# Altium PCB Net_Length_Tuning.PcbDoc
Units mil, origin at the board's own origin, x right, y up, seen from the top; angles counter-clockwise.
Board outline 6000 x 4000 mil, 4 copper layers (Component Side, Ground Plane, Power Plane, Solder Side); 10 components, 17 nets, 432 pads, 0 vias.
Unrouted connection lines stored in the file: 101.
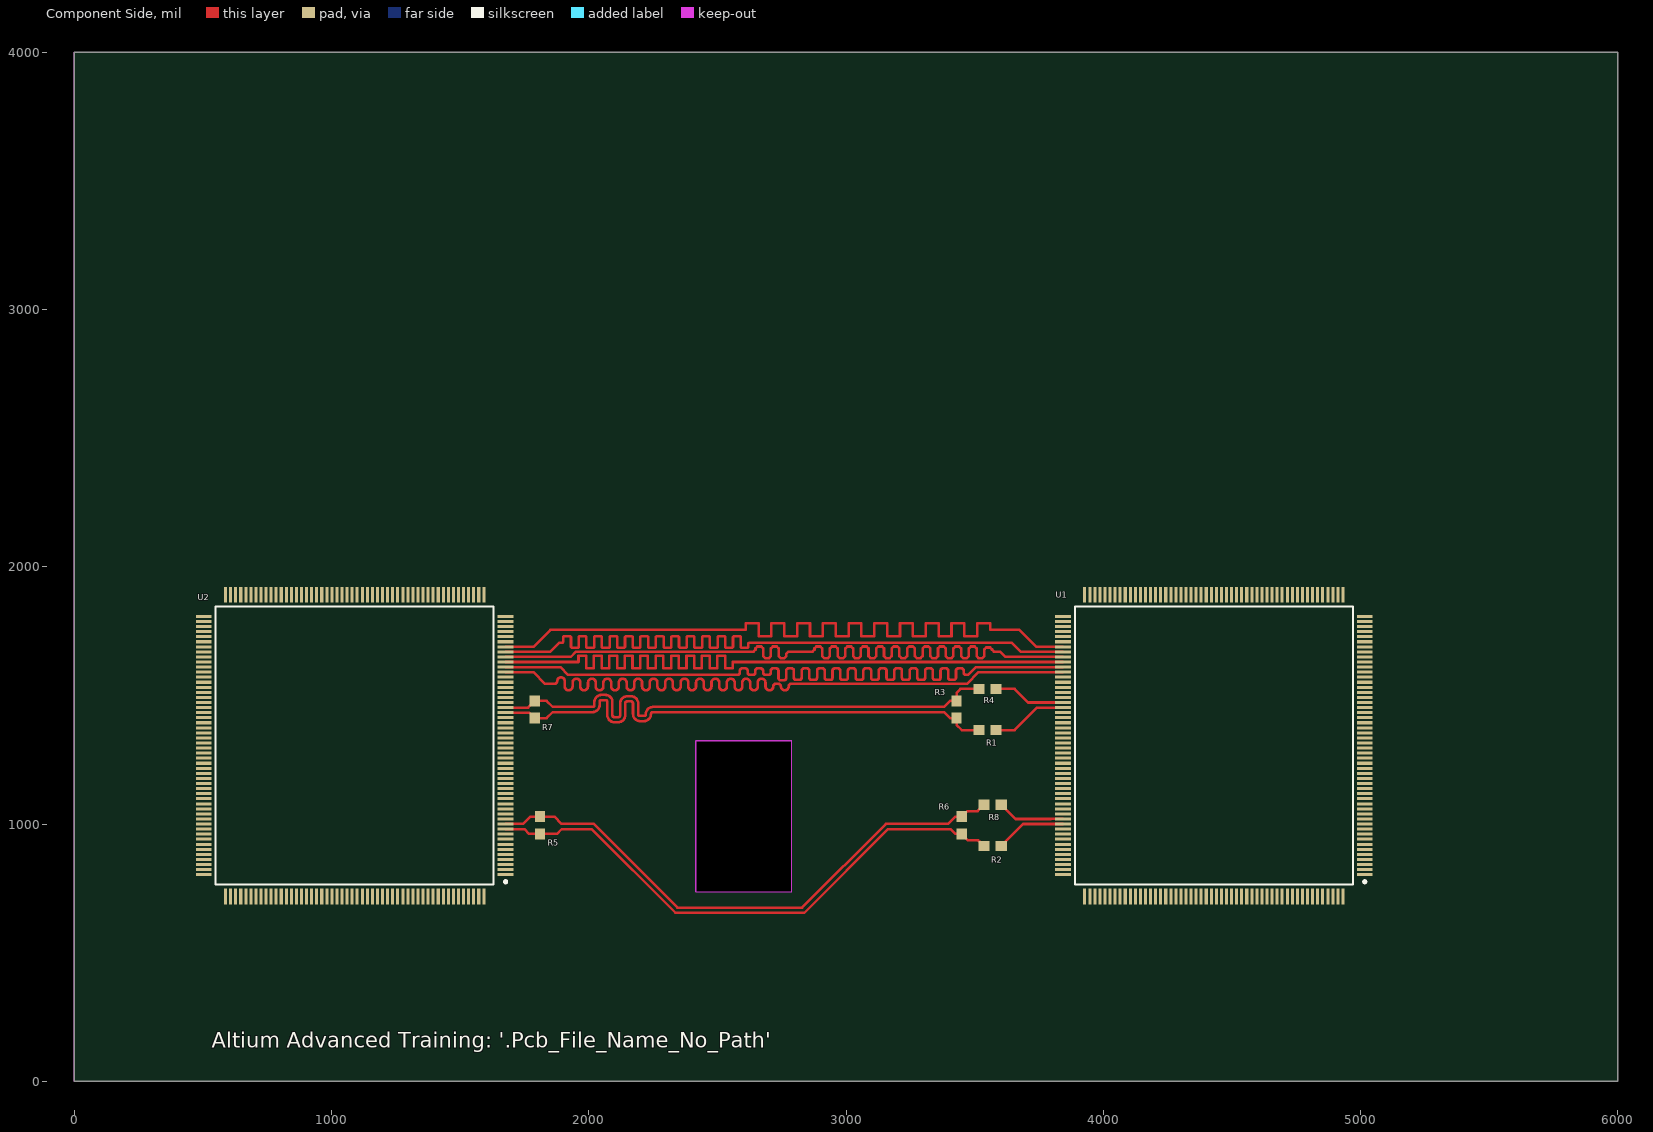
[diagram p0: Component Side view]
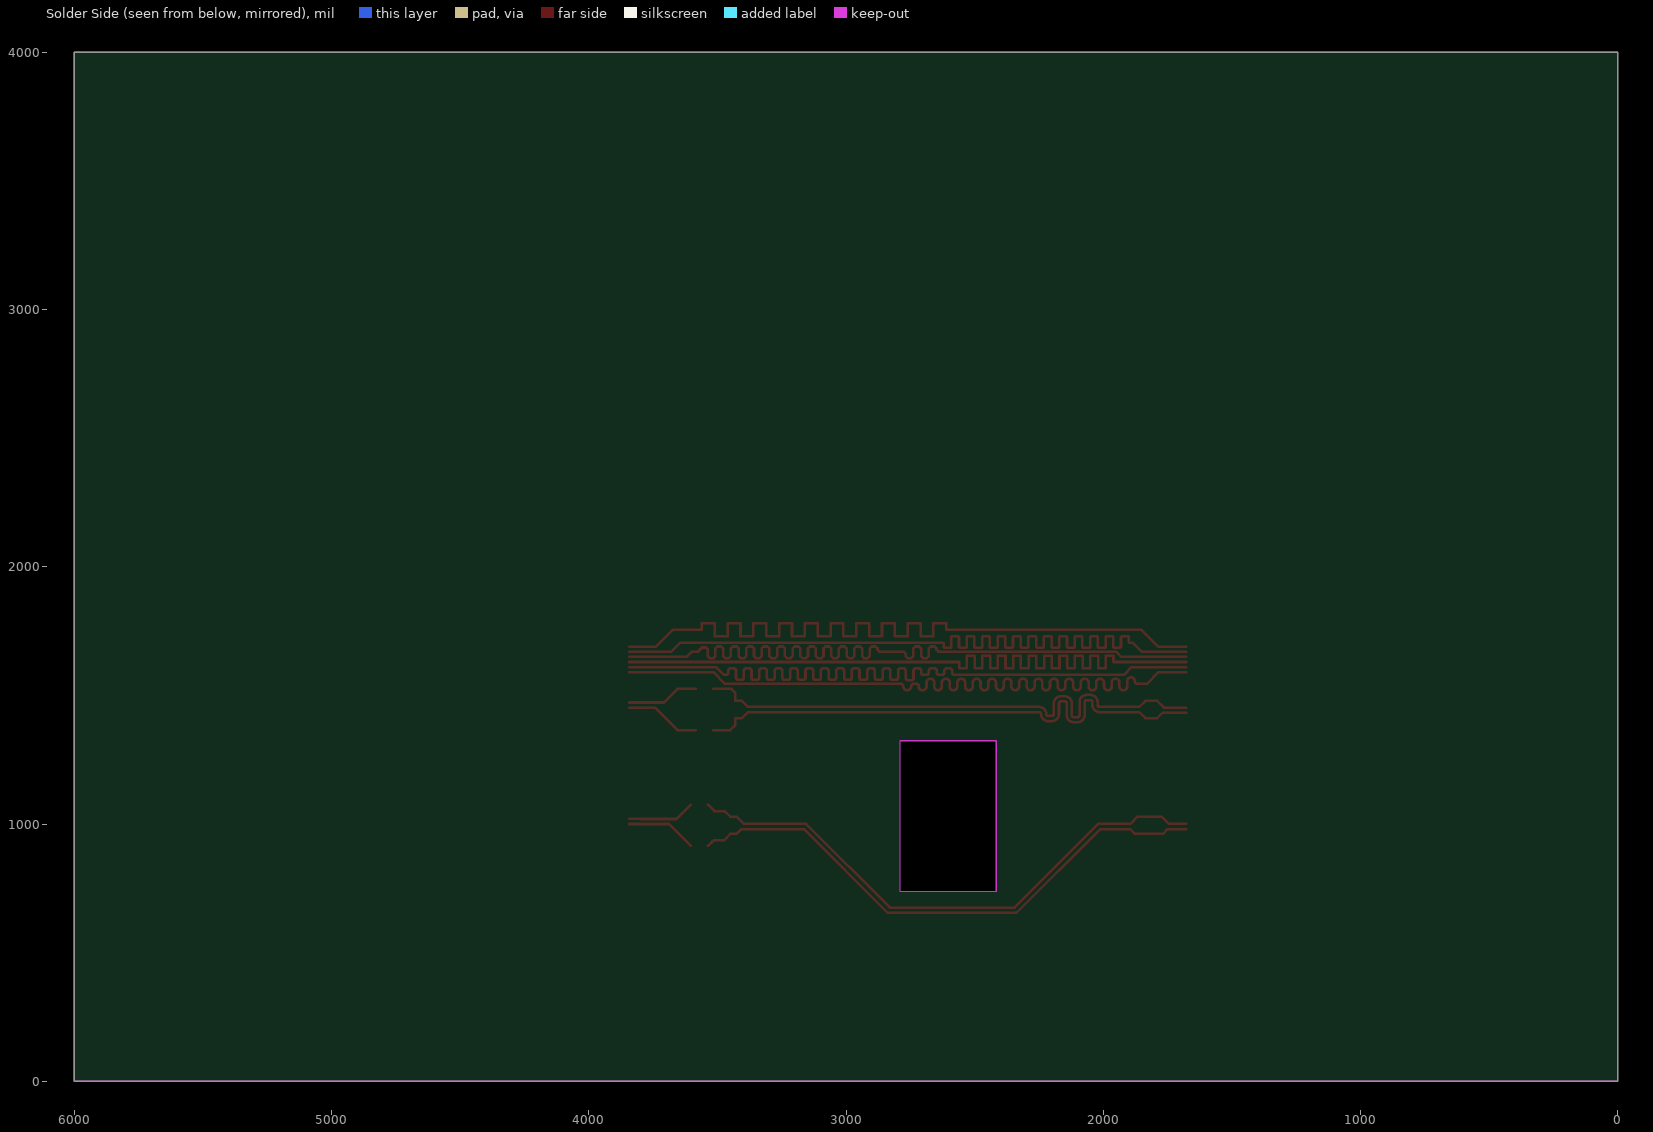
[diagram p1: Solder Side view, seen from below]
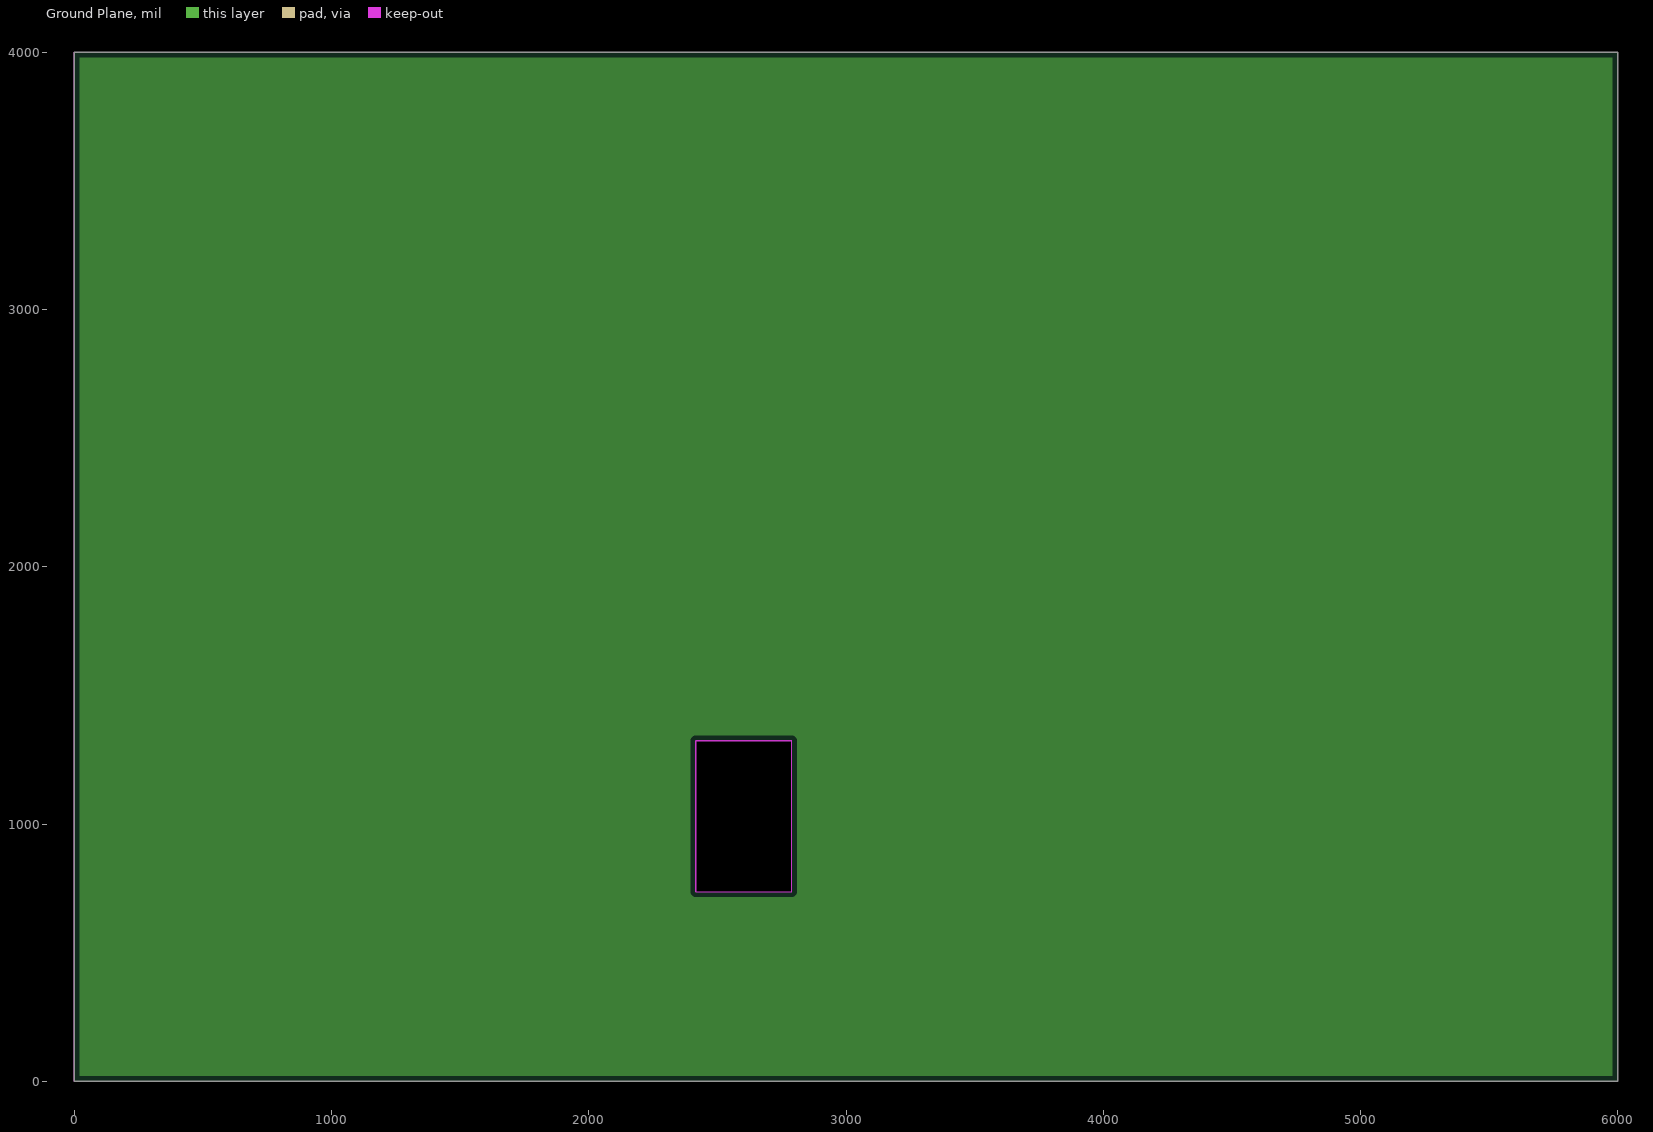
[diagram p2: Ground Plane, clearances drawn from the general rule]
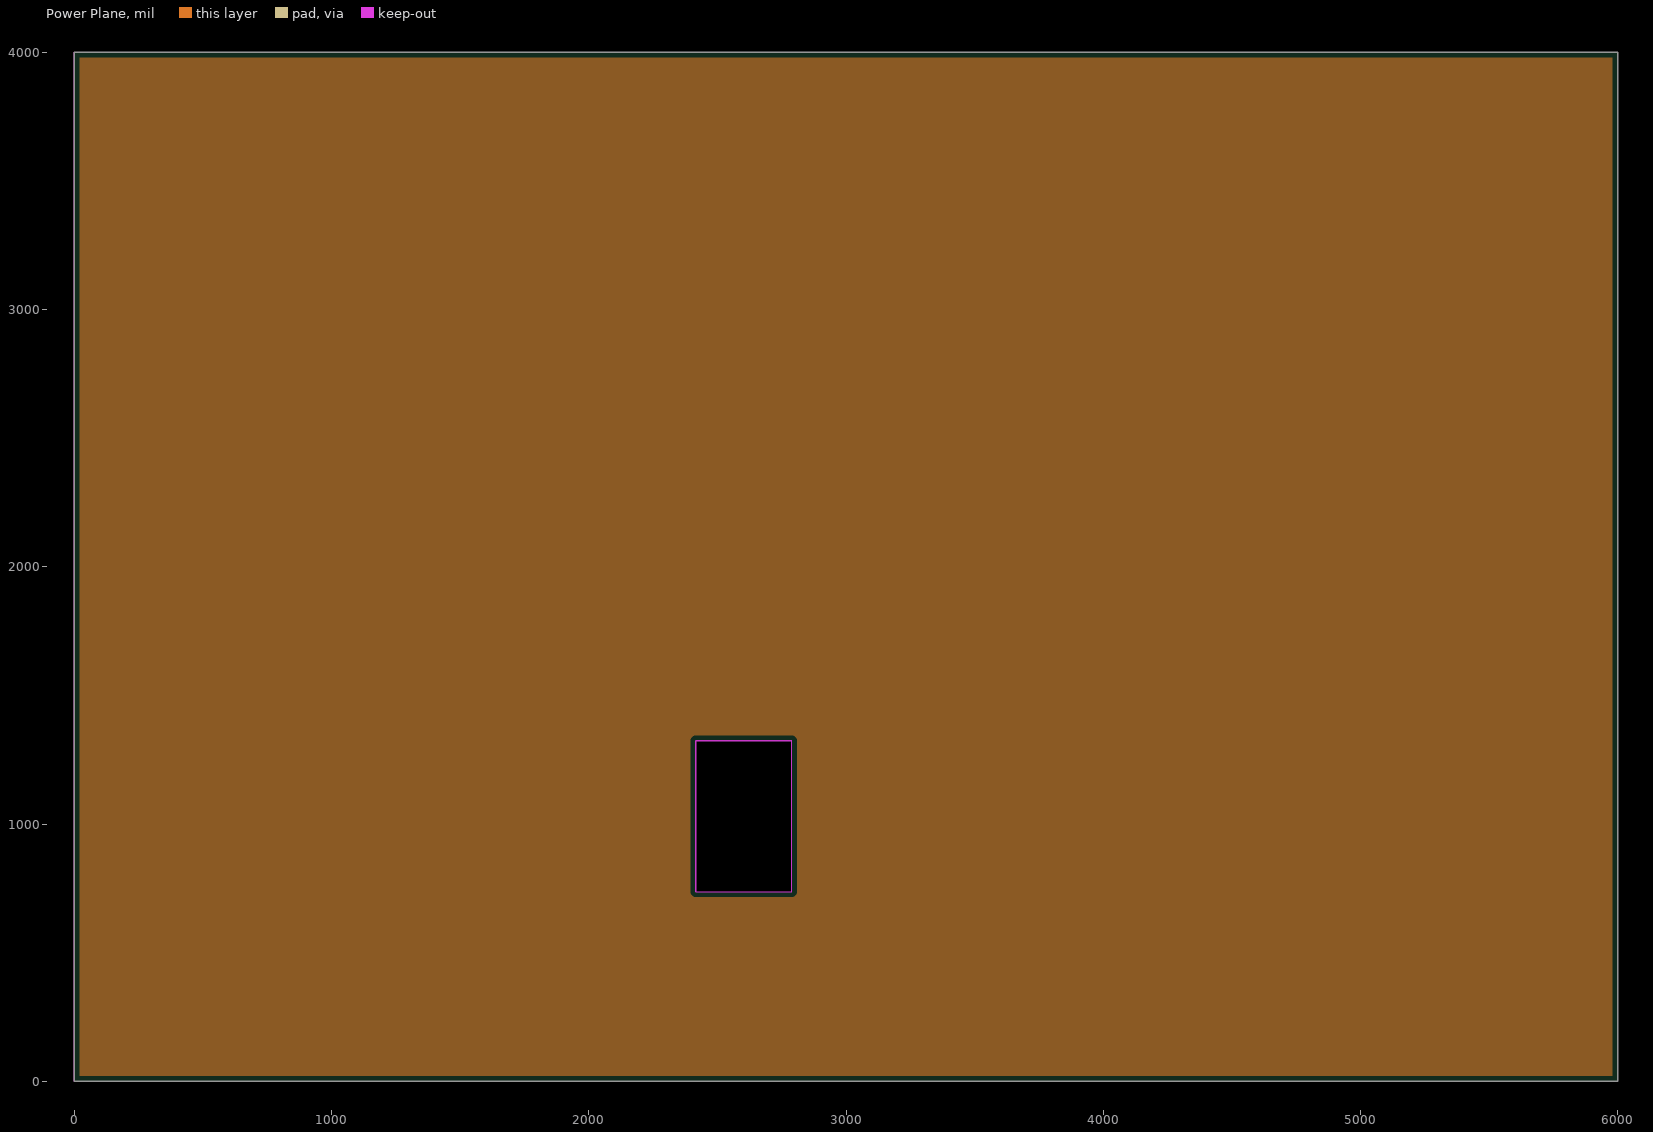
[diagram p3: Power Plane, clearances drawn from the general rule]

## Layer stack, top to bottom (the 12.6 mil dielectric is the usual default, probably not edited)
Top Solder: solder mask 0.4, Solder Resist, Dk 3.5
Component Side: signal copper 1.4
Dielectric1: core 12.6, FR-4, Dk 4.8
Ground Plane: plane copper 1.4
Dielectric2: prepreg 12.6, FR-4, Dk 4.8
Power Plane: plane copper 1.4
Dielectric3: core 12.6, FR-4, Dk 4.8
Solder Side: signal copper 1.4
Bottom Solder: solder mask 0.4, Solder Resist, Dk 3.5

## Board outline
0,0 6000,0 6000,4000 0,4000
cut-out: 2416,736 2789,736 2789,1324 2416,1324

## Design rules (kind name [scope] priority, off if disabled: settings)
Clearance [All] p1: gap=5 ignorepadtopadclearanceinfootprint=FALSE except(0: Arc-Hole Track-Hole SMDPad-Hole THPad-Hole Via-Hole Fill-Hole Poly-Hole Region-Hole Text-Hole)
DiffPairsRouting [All] p1: maxlimit=10 minlimit=10 mostfreqgap=10 toplayer_minwidth=10 toplayer_maxwidth=10 toplayer_prefwidth=10 bottomlayer_minwidth=10 bottomlayer_maxwidth=10 bottomlayer_prefwidth=10 maxuncoupledlength=500
FabricationTestPointUsage TestPointUsage [All] p1: valid=0 allowmultiple=FALSE
FabricationTestpoint Testpoint [All] p1: side=3 testpointundercomponent=TRUE minsize=40 maxsize=100 preferedsize=60 minholesize=0 maxholesize=40 preferedholesize=32 testpointgrid=1 allowsidetop=TRUE allowsidebottom=TRUE usegrid=TRUE gridtolerance=0.01
Length Length_LINE [InNetClass('LINE')] p1: maxlimit=3200 minlimit=2800
Length [InDifferentialPairClass('REC_DIFF')] p2: maxlimit=2200 minlimit=2100
MatchedLengths "MatchedLengths Within" [InDifferentialPairClass('REC_DIFF')] p1: tolerance=20 checknetsindiffpair=TRUE checkdiffpairvsdiffpair=FALSE checkxsignals=FALSE checkothers=FALSE
MatchedLengths "MatchedLengths Between" [InDifferentialPairClass('REC_DIFF')] p2: tolerance=50 checknetsindiffpair=FALSE checkdiffpairvsdiffpair=TRUE checkxsignals=TRUE checkothers=TRUE
MatchedLengths [InNetClass('LINE')] p3: tolerance=100 checknetsindiffpair=FALSE checkdiffpairvsdiffpair=TRUE checkxsignals=TRUE checkothers=TRUE
PlaneClearance [All] p1: clearance=20
PlaneConnect [All] p1: planeconnectstyle=Relief reliefexpansion=20 reliefentries=4 reliefconductorwidth=10 reliefairgap=10
PolygonConnect [All] p1: connectstyle=Relief reliefconductorwidth=10 reliefentries=4 polygonreliefangle="90 Angle" airgapwidth=10
RoomDefinition Length_Tune [InComponentClass('Length_Tune')] p1: confinementstyle=ConfineIn formatcopy=TRUE lockcomponents=FALSE outline 300,435 5295,435 5295,2185 300,2185
RoutingVias [All] p1: holewidth=28 width=50 viastyle="Through Hole" minholewidth=28 minwidth=50 maxholewidth=28 maxwidth=50
SignalStimulus SignalStimulus_N [InNet('DRV_N')] p1: kind=1 level=1 starttime=10,00 stoptime=60,00 periodtime=100,0
SignalStimulus SignalStimulus_POS [InNet('DRV_P')] p2: kind=1 level=0 starttime=10,00 stoptime=60,00 periodtime=100,0
SolderMaskExpansion [All] p1: expansion=4 istentingtop=FALSE
SupplyNets SupplyNets_VCC2 [InNet('VCC1V8')] p1: voltage=1,000
SupplyNets SupplyNets_VCC1 [InNet('VCC')] p2: voltage=3,000
SupplyNets SupplyNets_GND [InNet('GND')] p3: voltage=0,000
Width [All] p1: maxlimit=10 minlimit=10 preferedwidth=10
25 further rules are at their usual default settings.

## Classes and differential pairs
differential pair class REC_DIFF: REC REC2
net class LINE: Line1 Line2 Line3 Line4 Line5 Line6
differential pair REC2: +REC2_P -REC2_N
differential pair DRV2: +DRV2_P -DRV2_N
differential pair REC: +REC_P -REC_N
differential pair DRV: +DRV_P -DRV_N

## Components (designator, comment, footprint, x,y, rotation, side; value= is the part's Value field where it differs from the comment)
R1 "Res3" J1-0603 3550,1365 r180 top value=165
R2 "Res3" J1-0603 3570,915 r180 top value=165
R3 "Res3" J1-0603 3430,1445 r270 top value=140
R4 "Res3" J1-0603 3550,1525 r0 top value=165
R5 "Res3" J1-0603 1810,995 r90 top value=100
R6 "Res3" J1-0603 3450,995 r270 top value=140
R7 "Res3" J1-0603 1790,1445 r90 top value=100
R8 "Res3" J1-0603 3570,1075 r0 top value=165
U1 "XC2S200E-6PQ208C" PQ208 4430,1305 r180 top
U2 "XC2S200E-6PQ208C" PQ208 1090,1305 r180 top

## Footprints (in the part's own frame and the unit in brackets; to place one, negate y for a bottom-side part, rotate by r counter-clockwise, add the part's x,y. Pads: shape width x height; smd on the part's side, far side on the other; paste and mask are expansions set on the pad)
J1-0603 [mm] "Chip Resistor; Body 1.6 x 0.8 mm (LxW typ)"
  rect 1.1x1 smd: 1(-0.85,0) 2(0.85,0)
PQ208 [mm] "208-Pin Plastic Quad Flat Pack (PQ208)"
  rect 1.55x0.3 smd: 1(-14.9,12.75) 2(-14.9,12.25) 3(-14.9,11.75) 4(-14.9,11.25) 5(-14.9,10.75) 6(-14.9,10.25) 7(-14.9,9.75) 8(-14.9,9.25) 9(-14.9,8.75) 10(-14.9,8.25) 11(-14.9,7.75) 12(-14.9,7.25) 13(-14.9,6.75) 14(-14.9,6.25) 15(-14.9,5.75) 16(-14.9,5.25) 17(-14.9,4.75) 18(-14.9,4.25) 19(-14.9,3.75) 20(-14.9,3.25) 21(-14.9,2.75) 22(-14.9,2.25) 23(-14.9,1.75) 24(-14.9,1.25) 25(-14.9,0.75) 26(-14.9,0.25) 27(-14.9,-0.25) 28(-14.9,-0.75) 29(-14.9,-1.25) 30(-14.9,-1.75) 31(-14.9,-2.25) 32(-14.9,-2.75) 33(-14.9,-3.25) 34(-14.9,-3.75) 35(-14.9,-4.25) 36(-14.9,-4.75) 37(-14.9,-5.25) 38(-14.9,-5.75) 39(-14.9,-6.25) 40(-14.9,-6.75) 41(-14.9,-7.25) 42(-14.9,-7.75) 43(-14.9,-8.25) 44(-14.9,-8.75) 45(-14.9,-9.25) 46(-14.9,-9.75) 47(-14.9,-10.25) 48(-14.9,-10.75) 49(-14.9,-11.25) 50(-14.9,-11.75) 51(-14.9,-12.25) 52(-14.9,-12.75) 105(14.9,-12.75) 106(14.9,-12.25) 107(14.9,-11.75) 108(14.9,-11.25) 109(14.9,-10.75) 110(14.9,-10.25) 111(14.9,-9.75) 112(14.9,-9.25) 113(14.9,-8.75) 114(14.9,-8.25) 115(14.9,-7.75) 116(14.9,-7.25) 117(14.9,-6.75) 118(14.9,-6.25) 119(14.9,-5.75) 120(14.9,-5.25) 121(14.9,-4.75) 122(14.9,-4.25) 123(14.9,-3.75) 124(14.9,-3.25) 125(14.9,-2.75) 126(14.9,-2.25) 127(14.9,-1.75) 128(14.9,-1.25) 129(14.9,-0.75) 130(14.9,-0.25) 131(14.9,0.25) 132(14.9,0.75) 133(14.9,1.25) 134(14.9,1.75) 135(14.9,2.25) 136(14.9,2.75) 137(14.9,3.25) 138(14.9,3.75) 139(14.9,4.25) 140(14.9,4.75) 141(14.9,5.25) 142(14.9,5.75) 143(14.9,6.25) 144(14.9,6.75) 145(14.9,7.25) 146(14.9,7.75) 147(14.9,8.25) 148(14.9,8.75) 149(14.9,9.25) 150(14.9,9.75) 151(14.9,10.25) 152(14.9,10.75) 153(14.9,11.25) 154(14.9,11.75) 155(14.9,12.25) 156(14.9,12.75)
  rect 0.3x1.55 smd: 53(-12.75,-14.9) 54(-12.25,-14.9) 55(-11.75,-14.9) 56(-11.25,-14.9) 57(-10.75,-14.9) 58(-10.25,-14.9) 59(-9.75,-14.9) 60(-9.25,-14.9) 61(-8.75,-14.9) 62(-8.25,-14.9) 63(-7.75,-14.9) 64(-7.25,-14.9) 65(-6.75,-14.9) 66(-6.25,-14.9) 67(-5.75,-14.9) 68(-5.25,-14.9) 69(-4.75,-14.9) 70(-4.25,-14.9) 71(-3.75,-14.9) 72(-3.25,-14.9) 73(-2.75,-14.9) 74(-2.25,-14.9) 75(-1.75,-14.9) 76(-1.25,-14.9) 77(-0.75,-14.9) 78(-0.25,-14.9) 79(0.25,-14.9) 80(0.75,-14.9) 81(1.25,-14.9) 82(1.75,-14.9) 83(2.25,-14.9) 84(2.75,-14.9) 85(3.25,-14.9) 86(3.75,-14.9) 87(4.25,-14.9) 88(4.75,-14.9) 89(5.25,-14.9) 90(5.75,-14.9) 91(6.25,-14.9) 92(6.75,-14.9) 93(7.25,-14.9) 94(7.75,-14.9) 95(8.25,-14.9) 96(8.75,-14.9) 97(9.25,-14.9) 98(9.75,-14.9) 99(10.25,-14.9) 100(10.75,-14.9) 101(11.25,-14.9) 102(11.75,-14.9) 103(12.25,-14.9) 104(12.75,-14.9) 157(12.75,14.9) 158(12.25,14.9) 159(11.75,14.9) 160(11.25,14.9) 161(10.75,14.9) 162(10.25,14.9) 163(9.75,14.9) 164(9.25,14.9) 165(8.75,14.9) 166(8.25,14.9) 167(7.75,14.9) 168(7.25,14.9) 169(6.75,14.9) 170(6.25,14.9) 171(5.75,14.9) 172(5.25,14.9) 173(4.75,14.9) 174(4.25,14.9) 175(3.75,14.9) 176(3.25,14.9) 177(2.75,14.9) 178(2.25,14.9) 179(1.75,14.9) 180(1.25,14.9) 181(0.75,14.9) 182(0.25,14.9) 183(-0.25,14.9) 184(-0.75,14.9) 185(-1.25,14.9) 186(-1.75,14.9) 187(-2.25,14.9) 188(-2.75,14.9) 189(-3.25,14.9) 190(-3.75,14.9) 191(-4.25,14.9) 192(-4.75,14.9) 193(-5.25,14.9) 194(-5.75,14.9) 195(-6.25,14.9) 196(-6.75,14.9) 197(-7.25,14.9) 198(-7.75,14.9) 199(-8.25,14.9) 200(-8.75,14.9) 201(-9.25,14.9) 202(-9.75,14.9) 203(-10.25,14.9) 204(-10.75,14.9) 205(-11.25,14.9) 206(-11.75,14.9) 207(-12.25,14.9) 208(-12.75,14.9)
  silkscreen extent -15.03,-13.72 13.72,13.72

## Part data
R1 R2 R3 R4 R5 R6 R7 R8: "Resistor"
U1 U2: "Spartan-IIE 1.8V FPGA, 208-Pin PQFP, Standard Performance, Commercial Grade", Package Information="Latest Revision: ver1.1, Oct-2002", Package Reference=PQ208

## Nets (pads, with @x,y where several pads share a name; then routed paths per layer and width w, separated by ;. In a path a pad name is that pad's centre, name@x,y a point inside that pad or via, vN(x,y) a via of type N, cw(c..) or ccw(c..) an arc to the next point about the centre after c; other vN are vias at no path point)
DRV2_N: R8.2 U1.145 | length 263
  Component Side w10: R8.2 3658.9,1019.57 3796.4,1019.57 3796.72,1019.88 U1.145@3843.39,1019.88
DRV2_P: R2.1 U1.146 | length 275.1
  Component Side w10: R2.1 3688.35,999.88 U1.146
DRV_N: R4.2 U1.122 | length 281.7
  Component Side w10: R4.2 3655,1525 3707.68,1472.32 U1.122
DRV_P: R1.1 U1.123 | length 296.2
  Component Side w10: R1.1 3655,1365 3742.64,1452.64 U1.123
GND: U1.1 U1.12 U1.19 U1.25 U1.32 U1.39 U1.51 U1.65 U1.72 U1.79 U1.85 U1.92 U1.103 U1.117 U1.124 U1.131 U1.137 U1.144 U1.158 U1.170 U1.177 U1.183 U1.190 U1.197 U2.1 U2.12 U2.19 U2.25 U2.32 U2.39 U2.51 U2.65 U2.72 U2.79 U2.85 U2.92 U2.103 U2.117 U2.124 U2.131 U2.137 U2.144 U2.158 U2.170 U2.177 U2.183 U2.190 U2.197
LINE1: U1.111 U2.46 | length 3171.5
  Component Side w10: U2.46 1785,1688.86 1851.14,1755 2585,1755 2610,1755 2610,1780 2660,1780 2660,1755 2660,1730 2710,1730 2710,1755 2710,1780 2760,1780 2760,1755 2760,1730 2810,1730 2810,1755 2810,1780 2860,1780 2860,1755 2860,1730 2910,1730 2910,1755 2910,1780 2960,1780 2960,1755 2960,1730 3010,1730 3010,1755 3010,1780 3060,1780 3060,1755 3060,1730 3110,1730 3110,1755 3110,1780 3160,1780 3160,1755 3160,1730 3210,1730 3210,1755 3210,1780 3260,1780 3260,1755 3260,1730 3310,1730 3310,1755 3310,1780 3360,1780 3360,1755 3360,1730 3410,1730 3410,1755 3410,1780 3460,1780 3460,1755 3460,1730 3510,1730 3510,1755 3510,1780 3560,1780 3560,1755 3635,1755 3673.86,1755 3740,1688.86 U1.111
LINE2: U1.112 U2.45 | length 3185.7
  Component Side w10: U2.45 1850,1669.17 1885.83,1705 1897.83,1705 1900.83,1708 1900.83,1726.94 1903.83,1729.94 1927.83,1729.94 1930.83,1726.94 1930.83,1705 1930.83,1688.06 1933.83,1685.06 1957.83,1685.06 1960.83,1688.06 1960.83,1705 1960.83,1726.94 1963.83,1729.94 1987.83,1729.94 1990.83,1726.94 1990.83,1705 1990.83,1688.06 1993.83,1685.06 2017.83,1685.06 2020.83,1688.06 2020.83,1705 2020.83,1726.94 2023.83,1729.94 2047.83,1729.94 2050.83,1726.94 2050.83,1705 2050.83,1688.06 2053.83,1685.06 2077.83,1685.06 2080.83,1688.06 2080.83,1705 2080.83,1726.94 2083.83,1729.94 2107.83,1729.94 2110.83,1726.94 2110.83,1705 2110.83,1688.06 2113.83,1685.06 2137.83,1685.06 2140.83,1688.06 2140.83,1705 2140.83,1726.94 2143.83,1729.94 2167.83,1729.94 2170.83,1726.94 2170.83,1705 2170.83,1688.06 2173.83,1685.06 2197.83,1685.06 2200.83,1688.06 2200.83,1705 2200.83,1726.94 2203.83,1729.94 2227.83,1729.94 2230.83,1726.94 2230.83,1705 2230.83,1688.06 2233.83,1685.06 2257.83,1685.06 2260.83,1688.06 2260.83,1705 2260.83,1726.94 2263.83,1729.94 2287.83,1729.94 2290.83,1726.94 2290.83,1705 2290.83,1688.06 2293.83,1685.06 2317.83,1685.06 2320.83,1688.06 2320.83,1705 2320.83,1726.94 2323.83,1729.94 2347.83,1729.94 2350.83,1726.94 2350.83,1705 2350.83,1688.06 2353.83,1685.06 2377.83,1685.06 2380.83,1688.06 2380.83,1705 2380.83,1726.94 2383.83,1729.94 2407.83,1729.94 2410.83,1726.94 2410.83,1705 2410.83,1688.06 2413.83,1685.06 2437.83,1685.06 2440.83,1688.06 2440.83,1705 2440.83,1726.94 2443.83,1729.94 2467.83,1729.94 2470.83,1726.94 2470.83,1705 2470.83,1688.06 2473.83,1685.06 2497.83,1685.06 2500.83,1688.06 2500.83,1705 2500.83,1726.94 2503.83,1729.94 2527.83,1729.94 2530.83,1726.94 2530.83,1705 2530.83,1688.06 2533.83,1685.06 2557.83,1685.06 2560.83,1688.06 2560.83,1705 2560.83,1726.94 2563.83,1729.94 2587.83,1729.94 2590.83,1726.94 2590.83,1705 2590.83,1688.06 2593.83,1685.06 2617.83,1685.06 2620.83,1688.06 2620.83,1702 2623.83,1705 2645,1705 3644.17,1705 3680,1669.17 U1.112
LINE3: U1.113 U2.44 | length 3135.7
  Component Side w10: U2.44 1930,1649.49 1950.51,1670 2635.74,1670 2640.74,1670 2648.24,1677.5 2648.24,1682.5 2655.74,1690 2670.74,1690 2678.24,1682.5 2678.24,1652.5 2685.74,1645 2700.74,1645 2708.24,1652.5 2708.24,1682.5 2715.74,1690 2730.74,1690 2738.24,1682.5 2738.24,1652.5 2745.74,1645 2760.74,1645 2768.24,1652.5 2768.24,1662.5 2775.74,1670 2785.56,1670 2865.09,1670 2870.09,1670 2877.59,1677.5 2877.59,1682.5 2885.09,1690 2900.09,1690 2907.59,1682.5 2907.59,1652.3 2915.09,1644.8 2930.09,1644.8 2937.59,1652.3 2937.59,1682.5 2945.09,1690 2960.09,1690 2967.59,1682.5 2967.59,1652.3 2975.09,1644.8 2990.09,1644.8 2997.59,1652.3 2997.59,1682.5 3005.09,1690 3020.09,1690 3027.59,1682.5 3027.59,1652.3 3035.09,1644.8 3050.09,1644.8 3057.59,1652.3 3057.59,1682.5 3065.09,1690 3080.09,1690 3087.59,1682.5 3087.59,1652.3 3095.09,1644.8 3110.09,1644.8 3117.59,1652.3 3117.59,1682.5 3125.09,1690 3140.09,1690 3147.59,1682.5 3147.59,1652.3 3155.09,1644.8 3170.09,1644.8 3177.59,1652.3 3177.59,1682.5 3185.09,1690 3200.09,1690 3207.59,1682.5 3207.59,1652.3 3215.09,1644.8 3230.09,1644.8 3237.59,1652.3 3237.59,1682.5 3245.09,1690 3260.09,1690 3267.59,1682.5 3267.59,1652.3 3275.09,1644.8 3290.09,1644.8 3297.59,1652.3 3297.59,1682.5 3305.09,1690 3320.09,1690 3327.59,1682.5 3327.59,1652.3 3335.09,1644.8 3350.09,1644.8 3357.59,1652.3 3357.59,1682.5 3365.09,1690 3380.09,1690 3387.59,1682.5 3387.59,1652.3 3395.09,1644.8 3410.09,1644.8 3417.59,1652.3 3417.59,1682.5 3425.09,1690 3440.09,1690 3447.59,1682.5 3447.59,1652.3 3455.09,1644.8 3470.09,1644.8 3477.59,1652.3 3477.59,1682.5 3485.09,1690 3500.09,1690 3507.59,1682.5 3507.59,1652.3 3515.09,1644.8 3530.09,1644.8 3537.59,1652.3 3537.59,1678.7 3545.09,1686.2 3560.09,1686.2 3567.59,1678.7 3567.59,1677.5 3575.09,1670 3595,1670 3599.49,1670 3620,1649.49 U1.113
LINE4: U1.114 U2.43 | length 3166.8
  Component Side w10: U2.43 1945,1629.8 1960,1629.8 1960,1654.8 1990,1654.8 1990,1629.8 1990,1604.8 2020,1604.8 2020,1629.8 2020,1654.8 2050,1654.8 2050,1629.8 2050,1604.8 2080,1604.8 2080,1629.8 2080,1654.8 2110,1654.8 2110,1629.8 2110,1604.8 2140,1604.8 2140,1629.8 2140,1654.8 2170,1654.8 2170,1629.8 2170,1604.8 2200,1604.8 2200,1629.8 2200,1654.8 2230,1654.8 2230,1629.8 2230,1604.8 2260,1604.8 2260,1629.8 2260,1654.8 2290,1654.8 2290,1629.8 2290,1604.8 2320,1604.8 2320,1629.8 2320,1654.8 2350,1654.8 2350,1629.8 2350,1604.8 2380,1604.8 2380,1629.8 2380,1654.8 2410,1654.8 2410,1629.8 2410,1604.8 2440,1604.8 2440,1629.8 2440,1654.8 2470,1654.8 2470,1629.8 2470,1604.8 2500,1604.8 2500,1629.8 2500,1654.8 2530,1654.8 2530,1629.8 2530,1604.8 2560,1604.8 2560,1629.8 2585,1629.8 U1.114
LINE5: U1.115 U2.42 | length 3192.7
  Component Side w10: U2.42 1890,1610.12 1920.12,1580 2572.5,1580 2578.5,1580 ccw(c2578.5,1589) 2587.5,1589 2587.5,1596 cw(c2596.5,1596) 2596.5,1605 2608.5,1605 cw(c2608.5,1596) 2617.5,1596 2617.5,1589 ccw(c2626.5,1589) 2626.5,1580 2638.5,1580 ccw(c2638.5,1589) 2647.5,1589 2647.5,1596 cw(c2656.5,1596) 2656.5,1605 2668.5,1605 cw(c2668.5,1596) 2677.5,1596 2677.5,1589 ccw(c2686.5,1589) 2686.5,1580 2698.5,1580 ccw(c2698.5,1589) 2707.5,1589 2707.5,1596 cw(c2716.5,1596) 2716.5,1605 2728.5,1605 cw(c2728.5,1596) 2737.5,1596 2737.5,1580 2737.5,1567.64 ccw(c2746.5,1567.64) 2746.5,1558.64 2758.5,1558.64 ccw(c2758.5,1567.64) 2767.5,1567.64 2767.5,1580 2767.5,1596 cw(c2776.5,1596) 2776.5,1605 2788.5,1605 cw(c2788.5,1596) 2797.5,1596 2797.5,1580 2797.5,1569 ccw(c2806.5,1569) 2806.5,1560 2818.5,1560 ccw(c2818.5,1569) 2827.5,1569 2827.5,1580 2827.5,1596 cw(c2836.5,1596) 2836.5,1605 2848.5,1605 cw(c2848.5,1596) 2857.5,1596 2857.5,1580 2857.5,1569 ccw(c2866.5,1569) 2866.5,1560 2878.5,1560 ccw(c2878.5,1569) 2887.5,1569 2887.5,1580 2887.5,1596 cw(c2896.5,1596) 2896.5,1605 2908.5,1605 cw(c2908.5,1596) 2917.5,1596 2917.5,1580 2917.5,1569 ccw(c2926.5,1569) 2926.5,1560 2938.5,1560 ccw(c2938.5,1569) 2947.5,1569 2947.5,1580 2947.5,1596 cw(c2956.5,1596) 2956.5,1605 2968.5,1605 cw(c2968.5,1596) 2977.5,1596 2977.5,1580 2977.5,1569 ccw(c2986.5,1569) 2986.5,1560 2998.5,1560 ccw(c2998.5,1569) 3007.5,1569 3007.5,1580 3007.5,1596 cw(c3016.5,1596) 3016.5,1605 3028.5,1605 cw(c3028.5,1596) 3037.5,1596 3037.5,1580 3037.5,1569 ccw(c3046.5,1569) 3046.5,1560 3058.5,1560 ccw(c3058.5,1569) 3067.5,1569 3067.5,1580 3067.5,1596 cw(c3076.5,1596) 3076.5,1605 3088.5,1605 cw(c3088.5,1596) 3097.5,1596 3097.5,1580 3097.5,1569 ccw(c3106.5,1569) 3106.5,1560 3118.5,1560 ccw(c3118.5,1569) 3127.5,1569 3127.5,1580 3127.5,1596 cw(c3136.5,1596) 3136.5,1605 3148.5,1605 cw(c3148.5,1596) 3157.5,1596 3157.5,1580 3157.5,1569 ccw(c3166.5,1569) 3166.5,1560 3178.5,1560 ccw(c3178.5,1569) 3187.5,1569 3187.5,1580 3187.5,1596 cw(c3196.5,1596) 3196.5,1605 3208.5,1605 cw(c3208.5,1596) 3217.5,1596 3217.5,1580 3217.5,1569 ccw(c3226.5,1569) 3226.5,1560 3238.5,1560 ccw(c3238.5,1569) 3247.5,1569 3247.5,1580 3247.5,1596 cw(c3256.5,1596) 3256.5,1605 3268.5,1605 cw(c3268.5,1596) 3277.5,1596 3277.5,1580 3277.5,1569 ccw(c3286.5,1569) 3286.5,1560 3298.5,1560 ccw(c3298.5,1569) 3307.5,1569 3307.5,1580 3307.5,1596 cw(c3316.5,1596) 3316.5,1605 3328.5,1605 cw(c3328.5,1596) 3337.5,1596 3337.5,1580 3337.5,1569 ccw(c3346.5,1569) 3346.5,1560 3358.5,1560 ccw(c3358.5,1569) 3367.5,1569 3367.5,1580 3367.5,1596 cw(c3376.5,1596) 3376.5,1605 3388.5,1605 cw(c3388.5,1596) 3397.5,1596 3397.5,1580 3397.5,1569 ccw(c3406.5,1569) 3406.5,1560 3418.5,1560 ccw(c3418.5,1569) 3427.5,1569 3427.5,1580 3427.5,1596 cw(c3436.5,1596) 3436.5,1605 3448.5,1605 cw(c3448.5,1596) 3457.5,1596 3457.5,1589 ccw(c3466.5,1589) 3466.5,1580 3475,1580 3505.12,1610.12 U1.115
LINE6: U1.116 U2.41 | length 3133.9
  Component Side w10: U2.41 1785,1590.43 1830.43,1545 1862,1545 1867,1545 ccw(c1867,1555) 1877,1555 cw(c1892,1555) 1892,1570 cw(c1892,1555) 1907,1555 1907,1545 1907,1535 ccw(c1922,1535) 1922,1520 ccw(c1922,1535) 1937,1535 1937,1545 1937,1550 cw(c1952,1550) 1952,1565 cw(c1952,1550) 1967,1550 1967,1545 1967,1535 ccw(c1982,1535) 1982,1520 ccw(c1982,1535) 1997,1535 1997,1545 1997,1550 cw(c2012,1550) 2012,1565 cw(c2012,1550) 2027,1550 2027,1545 2027,1535 ccw(c2042,1535) 2042,1520 ccw(c2042,1535) 2057,1535 2057,1545 2057,1550 cw(c2072,1550) 2072,1565 cw(c2072,1550) 2087,1550 2087,1545 2087,1535 ccw(c2102,1535) 2102,1520 ccw(c2102,1535) 2117,1535 2117,1545 2117,1550 cw(c2132,1550) 2132,1565 cw(c2132,1550) 2147,1550 2147,1545 2147,1535 ccw(c2162,1535) 2162,1520 ccw(c2162,1535) 2177,1535 2177,1545 2177,1550 cw(c2192,1550) 2192,1565 cw(c2192,1550) 2207,1550 2207,1545 2207,1535 ccw(c2222,1535) 2222,1520 ccw(c2222,1535) 2237,1535 2237,1545 2237,1550 cw(c2252,1550) 2252,1565 cw(c2252,1550) 2267,1550 2267,1545 2267,1535 ccw(c2282,1535) 2282,1520 ccw(c2282,1535) 2297,1535 2297,1545 2297,1550 cw(c2312,1550) 2312,1565 cw(c2312,1550) 2327,1550 2327,1545 2327,1535 ccw(c2342,1535) 2342,1520 ccw(c2342,1535) 2357,1535 2357,1545 2357,1550 cw(c2372,1550) 2372,1565 cw(c2372,1550) 2387,1550 2387,1545 2387,1535 ccw(c2402,1535) 2402,1520 ccw(c2402,1535) 2417,1535 2417,1545 2417,1550 cw(c2432,1550) 2432,1565 cw(c2432,1550) 2447,1550 2447,1545 2447,1535 ccw(c2462,1535) 2462,1520 ccw(c2462,1535) 2477,1535 2477,1545 2477,1550 cw(c2492,1550) 2492,1565 cw(c2492,1550) 2507,1550 2507,1545 2507,1535 ccw(c2522,1535) 2522,1520 ccw(c2522,1535) 2537,1535 2537,1545 2537,1550 cw(c2552,1550) 2552,1565 cw(c2552,1550) 2567,1550 2567,1545 2567,1535 ccw(c2582,1535) 2582,1520 ccw(c2582,1535) 2597,1535 2597,1545 2597,1550 cw(c2612,1550) 2612,1565 cw(c2612,1550) 2627,1550 2627,1545 2627,1535 ccw(c2642,1535) 2642,1520 ccw(c2642,1535) 2657,1535 2657,1545 2657,1550 cw(c2672,1550) 2672,1565 cw(c2672,1550) 2687,1550 2687,1545 2687,1535 ccw(c2702,1535) 2702,1520 ccw(c2702,1535) 2717,1535 cw(c2727,1535) 2727,1545 2737,1545 cw(c2737,1535) 2747,1535 ccw(c2762,1535) 2762,1520 ccw(c2762,1535) 2777,1535 cw(c2787,1535) 2787,1545 2807,1545 2820,1545 2858.31,1545 2886.68,1545 2918.31,1545 2946.68,1545 2978.31,1545 3006.68,1545 3038.31,1545 3066.68,1545 3098.31,1545 3126.68,1545 3158.31,1545 3186.68,1545 3218.31,1545 3246.68,1545 3278.31,1545 3306.68,1545 3338.31,1545 3366.68,1545 3470,1545 3515.43,1590.43 U1.116
REC2_N: R5.2 R6.1 R8.1 U2.11 | length 2183.7
  Component Side w10: U2.11@1676.61,1000.2 1745.2,1000.2 1773.46,1028.46 R5.2 1866.54,1028.46 1894.8,1000.2 2019.8,1000.2 2345,675 2829.8,675 3155,1000.2 3396.73,1000.2 3425,1028.46 R6.1 3471.54,1050 3511.54,1050 R8.1
REC2_P: R2.2 R5.1 R6.2 U2.10 | length 2171.8
  Component Side w10: U2.10 1749.8,980.2 1768.46,961.54 R5.1 1876.34,961.54 1895,980.2 2011.52,980.2 2336.72,655 2375,655 2838.09,655 3163.28,980.2 3406.34,980.2 3425,961.54 R6.2 3475,936.54 3513.46,936.54 3520,930 3521.54,930 R2.2
REC_N: R3.1 R4.1 R7.2 U2.34 | length 2158.7
  Component Side w10: U2.34 1764.17,1452.64 R7.2 1836.54,1478.46 1860,1455 1999.49,1455 2014.49,1455 ccw(c2014.49,1462.5) 2021.99,1462.5 2021.99,1474.21 cw(c2049.49,1474.21) 2049.49,1501.71 2064.49,1501.71 cw(c2064.49,1474.21) 2091.99,1474.21 2091.99,1422.87 ccw(c2099.49,1422.87) 2099.49,1415.37 2114.49,1415.37 ccw(c2114.49,1422.87) 2121.99,1422.87 2121.99,1469.18 cw(c2149.49,1469.18) 2149.49,1496.68 2164.49,1496.68 cw(c2164.49,1469.18) 2191.99,1469.18 2191.99,1427.5 ccw(c2199.49,1427.5) 2199.49,1420 2214.49,1420 ccw(c2214.49,1427.5) 2221.99,1427.5 cw(c2249.49,1427.5) 2249.49,1455 2343.72,1455 3381.54,1455 3405,1478.46 R3.1 3430,1510 3445,1525 R4.1
REC_P: R1.2 R3.2 R7.1 U2.33 | length 2154
  Component Side w10: U2.33 1768.58,1432.95 R7.1 1836.54,1411.54 1860,1435 1999.49,1435 2014.49,1435 ccw(c2014.49,1462.5) 2041.99,1462.5 2041.99,1474.21 cw(c2049.49,1474.21) 2049.49,1481.71 2064.49,1481.71 cw(c2064.49,1474.21) 2071.99,1474.21 2071.99,1422.87 ccw(c2099.49,1422.87) 2099.49,1395.37 2114.49,1395.37 ccw(c2114.49,1422.87) 2141.99,1422.87 2141.99,1469.18 cw(c2149.49,1469.18) 2149.49,1476.68 2164.49,1476.68 cw(c2164.49,1469.18) 2171.99,1469.18 2171.99,1427.5 ccw(c2199.49,1427.5) 2199.49,1400 2214.49,1400 ccw(c2214.49,1427.5) 2241.99,1427.5 cw(c2249.49,1427.5) 2249.49,1435 2343.72,1435 3381.54,1435 3405,1411.54 R3.2 3430,1385 3450,1365 R1.2
VCC: U1.13 U1.26 U1.38 U1.53 U1.66 U1.78 U1.91 U1.105 U1.118 U1.130 U1.143 U1.156 U1.171 U1.184 U1.196 U1.208 U2.13 U2.26 U2.38 U2.53 U2.66 U2.78 U2.91 U2.105 U2.118 U2.130 U2.143 U2.156 U2.171 U2.184 U2.196 U2.208
VCC1V8: U1.14 U1.28 U1.37 U1.67 U1.76 U1.90 U1.119 U1.128 U1.142 U1.172 U1.186 U1.195 U2.14 U2.28 U2.37 U2.67 U2.76 U2.90 U2.119 U2.128 U2.142 U2.172 U2.186 U2.195
pads on no net: U1.2 U1.3 U1.4 U1.5 U1.6 U1.7 U1.8 U1.9 U1.10 U1.11 U1.15 U1.16 U1.17 U1.18 U1.20 U1.21 U1.22 U1.23 U1.24 U1.27 U1.29 U1.30 U1.31 U1.33 U1.34 U1.35 U1.36 U1.40 U1.41 U1.42 U1.43 U1.44 U1.45 U1.46 U1.47 U1.48 U1.49 U1.50 U1.52 U1.54 U1.55 U1.56 U1.57 U1.58 U1.59 U1.60 U1.61 U1.62 U1.63 U1.64 U1.68 U1.69 U1.70 U1.71 U1.73 U1.74 U1.75 U1.77 U1.80 U1.81 U1.82 U1.83 U1.84 U1.86 U1.87 U1.88 U1.89 U1.93 U1.94 U1.95 U1.96 U1.97 U1.98 U1.99 U1.100 U1.101 U1.102 U1.104 U1.106 U1.107 U1.108 U1.109 U1.110 U1.120 U1.121 U1.125 U1.126 U1.127 U1.129 U1.132 U1.133 U1.134 U1.135 U1.136 U1.138 U1.139 U1.140 U1.141 U1.147 U1.148 U1.149 U1.150 U1.151 U1.152 U1.153 U1.154 U1.155 U1.157 U1.159 U1.160 U1.161 U1.162 U1.163 U1.164 U1.165 U1.166 U1.167 U1.168 U1.169 U1.173 U1.174 U1.175 U1.176 U1.178 U1.179 U1.180 U1.181 U1.182 U1.185 U1.187 U1.188 U1.189 U1.191 U1.192 U1.193 U1.194 U1.198 U1.199 U1.200 U1.201 U1.202 U1.203 U1.204 U1.205 U1.206 U1.207 U2.2 U2.3 U2.4 U2.5 U2.6 U2.7 U2.8 U2.9 U2.15 U2.16 U2.17 U2.18 U2.20 U2.21 U2.22 U2.23 U2.24 U2.27 U2.29 U2.30 U2.31 U2.35 U2.36 U2.40 U2.47 U2.48 U2.49 U2.50 U2.52 U2.54 U2.55 U2.56 U2.57 U2.58 U2.59 U2.60 U2.61 U2.62 U2.63 U2.64 U2.68 U2.69 U2.70 U2.71 U2.73 U2.74 U2.75 U2.77 U2.80 U2.81 U2.82 U2.83 U2.84 U2.86 U2.87 U2.88 U2.89 U2.93 U2.94 U2.95 U2.96 U2.97 U2.98 U2.99 U2.100 U2.101 U2.102 U2.104 U2.106 U2.107 U2.108 U2.109 U2.110 U2.111 U2.112 U2.113 U2.114 U2.115 U2.116 U2.120 U2.121 U2.122 U2.123 U2.125 U2.126 U2.127 U2.129 U2.132 U2.133 U2.134 U2.135 U2.136 U2.138 U2.139 U2.140 U2.141 U2.145 U2.146 U2.147 U2.148 U2.149 U2.150 U2.151 U2.152 U2.153 U2.154 U2.155 U2.157 U2.159 U2.160 U2.161 U2.162 U2.163 U2.164 U2.165 U2.166 U2.167 U2.168 U2.169 U2.173 U2.174 U2.175 U2.176 U2.178 U2.179 U2.180 U2.181 U2.182 U2.185 U2.187 U2.188 U2.189 U2.191 U2.192 U2.193 U2.194 U2.198 U2.199 U2.200 U2.201 U2.202 U2.203 U2.204 U2.205 U2.206 U2.207

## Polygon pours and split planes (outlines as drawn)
GND on Ground Plane (split plane): 5979.9,20.1 20.1,20.1 20.1,3979.9 5979.9,3979.9
VCC on Power Plane (split plane): 5979.9,20.1 20.1,20.1 20.1,3979.9 5979.9,3979.9

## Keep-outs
Keep-Out Layer:
  lines w2: 0,0 6000,0 6000,4000 0,4000 0,0 ; 2416,736 2789,736 2789,1324 2416,1324 2416,736

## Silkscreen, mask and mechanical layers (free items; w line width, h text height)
Top Overlay:
  text "Altium Advanced Training: '.Pcb_File_Name_No_Path'" at 535,129.99 h60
